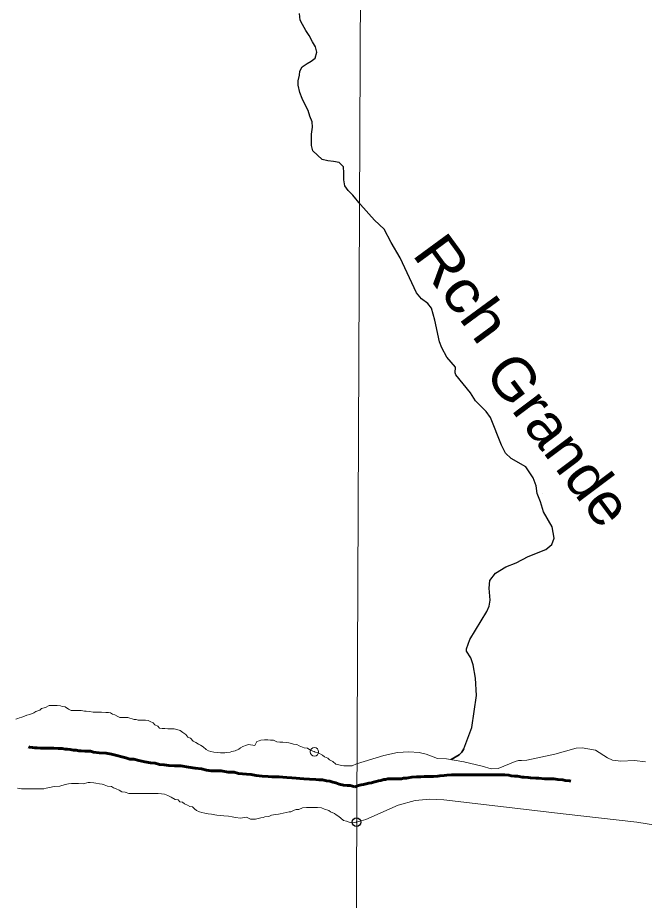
# Model space of a CAD drawing. Extents: x 553962 to 842807, y 8883888 to 9032388.
# Drawn here: x 660513 to 667945, y 8920889 to 8931350 of the extents above; entities that cross this region are included whole.
import ezdxf

# ---------------------------------------------------------------- set-up
doc = ezdxf.new("R2010")
doc.units = 0
doc.header["$LTSCALE"] = 200
doc.header["$PDMODE"] = 32
doc.header["$PDSIZE"] = 100
doc.linetypes.add('LONG_DASH_SHORT_DASH', pattern=[9.9, 6, -1.2, 1.5, -1.2])
for name, color, linetype, lineweight in [('1', 7, 'Continuous', 13), ('24', 7, 'Continuous', 25), ('25', 7, 'Continuous', 13), ('57', 7, 'Continuous', 13), ('7', 7, 'LONG_DASH_SHORT_DASH', 60)]:
    doc.layers.add(name, color=color, linetype=linetype, lineweight=lineweight)
doc.layers.add('49', color=7, linetype='Continuous')

msp = doc.modelspace()

# ---------------------------------------------------------------- linework, layer by layer
at = {"layer": '1'}
msp.add_lwpolyline([(664968.2, 9023436.8), (664657.1, 8949509), (664397.1, 8890880.2)], dxfattribs=at)
at = {"layer": '24'}
msp.add_line((666737.2, 8925710.7), (666737.9, 8925710.1), dxfattribs=at)
for points in [[(663996.4, 8929884.7), (663996.8, 8929971.2), (664009.7, 8930053.7), (664007.4, 8930113.8), (663977.7, 8930184), (663958, 8930249.2), (663913.4, 8930334.5), (663886.1, 8930392.2), (663858.9, 8930462.4), (663839.3, 8930550.1), (663839.5, 8930602.7), (663854.8, 8930667.7), (663860.1, 8930715.2), (663887.8, 8930767.6), (663945.6, 8930807.4), (663995.7, 8930834.6), (664041, 8930869.4), (664061.3, 8930941.9), (664046.6, 8931004.6), (664011.8, 8931064.8), (663969.6, 8931137.6), (663929.9, 8931197.9), (663890.2, 8931270.7), (663862.9, 8931320.8), (663855.7, 8931401)], [(665884.6, 8926902.1), (665710.7, 8927118.6), (665703.5, 8927141.6), (665707.3, 8927207.3), (665604.7, 8927327.2), (665543.5, 8927435.1), (665514.2, 8927508.8), (665462.2, 8927764.8), (665420, 8927905.9), (665377.5, 8927963.9), (665304.4, 8928016.2), (665243.3, 8928087.8), (665050.8, 8928503.2), (664941.5, 8928686.6), (664858.3, 8928844.6), (664746.5, 8928950.8), (664577.8, 8929135.4), (664488.9, 8929245.3), (664434.1, 8929300.7), (664391.8, 8929358.5), (664382.1, 8929428.6), (664380, 8929511.2), (664377.8, 8929583.8), (664325.5, 8929634.1), (664258, 8929647), (664193, 8929654.8), (664125.5, 8929670.2), (664070.7, 8929720.5), (664013.4, 8929773.4), (663996.1, 8929836.1), (663996.4, 8929884.7)], [(665654.1, 8922558.1), (665747.4, 8922613.4), (665782.6, 8922644.9), (665804.2, 8922685), (665898.2, 8922937), (665956.6, 8923316.8), (665944.3, 8923521), (665915.9, 8923680.3), (665887.1, 8923762.6), (665837.8, 8923840.4), (665834.9, 8923868.6), (665876, 8923981.1), (666075.9, 8924311.2), (666104.4, 8924374.8), (666118.2, 8924447.8), (666103.2, 8924589.1), (666111.8, 8924680), (666180.2, 8924767.7), (666303.3, 8924840.7), (666423.2, 8924888.8), (666567, 8924965.4), (666778.1, 8925046.5), (666849.4, 8925104.6), (666875.5, 8925182.5), (666852.3, 8925317.2), (666747.4, 8925494.9), (666714.9, 8925611.2), (666674, 8925709.5), (666660.9, 8925800.8), (666626.8, 8925897.6), (666539.3, 8926027.5), (666367.3, 8926123.4), (666298.2, 8926188.4), (666251.5, 8926283.4), (666120.6, 8926610.3), (666067.4, 8926681.3), (665942.6, 8926807.9), (665884.6, 8926902.1)], [(665804.2, 8922685), (665782.6, 8922644.9), (665747.4, 8922613.4), (665654.1, 8922558.1)]]:
    msp.add_lwpolyline(points, dxfattribs=at)
msp.add_point((664531.1, 8921815.4), dxfattribs=at)
at = {"layer": '25'}
for points in [[(660493.9, 8923037.8), (660516.5, 8923042.7), (660536.6, 8923052.6), (660564.1, 8923059.9), (660596.7, 8923069.7), (660624.3, 8923084.5), (660656.9, 8923089.3), (660704.6, 8923109.1), (660729.7, 8923126.4), (660774.9, 8923143.6), (660797.5, 8923161), (660842.6, 8923175.7), (660885.3, 8923198), (660915.3, 8923197.8), (660940.3, 8923197.6), (660980.4, 8923197.3), (661020.4, 8923194.6), (661042.8, 8923186.9), (661077.8, 8923181.7), (661115.1, 8923156.4), (661147.5, 8923138.7), (661187.5, 8923138.4), (661207.5, 8923138.3), (661245, 8923138), (661265, 8923137.9), (661305, 8923132.6), (661327.5, 8923130), (661365, 8923127.2), (661407.5, 8923119.4), (661447.5, 8923119.2), (661472.5, 8923119), (661507.5, 8923118.8), (661557.5, 8923115.9), (661592.5, 8923113.2), (661615, 8923110.5), (661637.4, 8923095.4), (661667.3, 8923087.7), (661702.2, 8923067.4), (661724.6, 8923057.2), (661754.6, 8923057), (661819.7, 8923056.6), (661897, 8923033.6), (661919.5, 8923030.9), (661942, 8923025.8), (661972, 8923023.1), (662009.5, 8923022.8), (662029.5, 8923022.7), (662062, 8923019.9), (662086.9, 8923009.8), (662121.8, 8922992), (662141.6, 8922969.4), (662176.5, 8922954.1), (662193.8, 8922928.9), (662226.3, 8922923.7), (662258.8, 8922923.5), (662293.8, 8922923.3), (662313.9, 8922923.2), (662333.9, 8922923), (662371.4, 8922922.8), (662401.3, 8922912.6), (662438.7, 8922899.8), (662471.1, 8922879.6), (662508.4, 8922854.3), (662530.7, 8922824.1), (662563.1, 8922808.8), (662592.9, 8922776.1), (662625.2, 8922758.4), (662657.6, 8922738.1), (662680, 8922728), (662712.4, 8922707.7), (662747.2, 8922674.9), (662777.1, 8922659.7), (662804.5, 8922652), (662839.5, 8922644.3), (662884.5, 8922639), (662917, 8922638.8), (662937, 8922638.6), (662969.5, 8922638.4), (662992, 8922640.8), (663032.1, 8922645.5), (663054.6, 8922652.9), (663094.7, 8922662.6), (663134.9, 8922679.9), (663155, 8922697.3), (663182.6, 8922712.1), (663225.3, 8922729.4), (663250.3, 8922734.2), (663325.3, 8922723.7), (663348.2, 8922771.1), (663378.2, 8922778.4)], [(663378.2, 8922778.4), (663398.3, 8922785.8), (663440.8, 8922790.5), (663478.4, 8922790.3), (663513.3, 8922787.5), (663545.9, 8922787.3), (663588.2, 8922767), (663623.2, 8922764.3), (663658.2, 8922764.1), (663698.2, 8922761.3), (663730.7, 8922753.6), (663760.7, 8922748.3), (663785.6, 8922740.7), (663825.6, 8922735.4), (663850.5, 8922720.2), (663890.4, 8922704.9), (663912.8, 8922697.3), (663950.3, 8922692), (663977.7, 8922674.3), (664032.5, 8922648.9), (664084.9, 8922631), (664127.3, 8922608.2), (664152.1, 8922590.5), (664192, 8922572.8), (664211.9, 8922552.6), (664249.2, 8922534.8), (664286.5, 8922504.5), (664309, 8922496.9), (664348.9, 8922486.6), (664381.4, 8922481.4), (664416.4, 8922481.1), (664436.4, 8922481), (664461.5, 8922483.3), (664481.5, 8922483.2), (664531.1, 8922504.7), (664855.7, 8922606.1), (665018.2, 8922640.1), (665151.9, 8922649.8), (665276.6, 8922642.6), (665359.5, 8922619.8)], [(665807.2, 8922530.5), (665805.3, 8922529), (666021.2, 8922480.8), (666128.1, 8922448.4), (666212.6, 8922450.2), (666414.1, 8922533.6), (666451.7, 8922544.9), (666486.4, 8922546.2), (666551.6, 8922551.4), (666883.2, 8922619.3), (667134.9, 8922692.2), (667207.8, 8922696.8), (667366, 8922668.8), (667507, 8922579.6), (667567.9, 8922550.4), (667666.3, 8922536.7), (667827.1, 8922544.8), (667960.2, 8922528.3)], [(665359.5, 8922619.8), (665492.3, 8922568.3), (665600, 8922565.9), (665805.3, 8922529)], [(662255.4, 8922147.4), (662220.4, 8922150.2), (662177.9, 8922153), (662152.9, 8922153.1), (662112.9, 8922153.4), (662087.9, 8922153.6), (662027.9, 8922154), (661975.4, 8922154.3), (661940.3, 8922154.5), (661900.3, 8922154.8), (661872.8, 8922155), (661830.3, 8922155.3), (661790.4, 8922170.6), (661750.4, 8922175.8), (661715.6, 8922196.1), (661683.2, 8922211.3), (661648.2, 8922221.6), (661625.8, 8922236.7), (661578.3, 8922242.1), (661538.5, 8922257.3), (661516, 8922265), (661483.5, 8922270.2), (661441.1, 8922278), (661416.1, 8922283.2), (661373.6, 8922283.5), (661351.1, 8922283.6), (661290.9, 8922269), (661233.5, 8922274.4), (661178.4, 8922274.7), (661150.9, 8922272.4), (661115.8, 8922267.6), (661075.8, 8922260.4), (661015.6, 8922243.3), (660945.6, 8922238.7), (660892.9, 8922224.1), (660852.8, 8922216.8), (660825.3, 8922212), (660772.8, 8922209.8), (660732.7, 8922210.1), (660682.7, 8922210.4), (660637.7, 8922210.7), (660610.2, 8922210.9), (660560.2, 8922211.2), (660510.2, 8922219.1)], [(663096.2, 8921869), (663056.2, 8921876.8), (663013.8, 8921884.6), (662958.8, 8921889.9), (662913.8, 8921895.2), (662873.8, 8921898), (662851.3, 8921903.2), (662811.4, 8921908.4), (662773.9, 8921913.7), (662733.9, 8921921.5), (662696.5, 8921929.2), (662671.5, 8921936.9), (662634.1, 8921952.2), (662611.8, 8921972.3), (662586.9, 8921997.5), (662557, 8922002.8), (662529.6, 8922017.9), (662492.2, 8922033.2), (662469.8, 8922050.9), (662434.8, 8922056.1), (662415, 8922081.3), (662380, 8922084), (662332.7, 8922111.9), (662292.8, 8922132.2), (662255.4, 8922147.4)], [(670613, 8921062.4), (670594.6, 8921075.1), (670505.7, 8921092.1), (670378.9, 8921097.7), (670172.5, 8921136.1), (669790.2, 8921268), (669181.6, 8921455.5), (668940.4, 8921522.2), (668553.3, 8921609.1), (668470.6, 8921646), (668322.8, 8921739.3), (667855.1, 8921816.8), (666980.9, 8921915.9), (665565.9, 8922078.1), (665402.5, 8922087.8), (665227.8, 8922071.5), (665027.5, 8922015.6), (664640.9, 8921845.5), (664531.1, 8921815.4)], [(664531.1, 8921815.4), (664483.8, 8921807.2), (664446.4, 8921815), (664411.5, 8921827.8), (664379, 8921835.5), (664344.2, 8921863.2), (664321.8, 8921880.9), (664292, 8921903.7), (664269.6, 8921918.8), (664224.7, 8921936.6), (664202.3, 8921954.3), (664152.4, 8921969.7), (664117.5, 8921984.9), (664070, 8921987.7), (664027.5, 8921988), (663982.5, 8921988.3), (663937.5, 8921988.6), (663892.4, 8921983.9), (663849.7, 8921964.2), (663814.7, 8921964.4), (663792.2, 8921957), (663754.5, 8921937.2), (663734.5, 8921937.4), (663696.9, 8921930.1), (663661.8, 8921922.8), (663626.8, 8921915.6), (663606.7, 8921910.7), (663571.7, 8921905.9), (663524.1, 8921898.7), (663491.5, 8921883.9), (663446.4, 8921879.2), (663426.3, 8921871.8), (663396.3, 8921867), (663366.2, 8921857.2), (663333.7, 8921852.4), (663311.1, 8921850.1), (663276.1, 8921850.3), (663226.3, 8921875.7), (663156.2, 8921863.6), (663096.2, 8921869)]]:
    msp.add_lwpolyline(points, dxfattribs=at)
msp.add_point((664531.1, 8921815.4), dxfattribs=at)
at = {"layer": '57'}
for points in [[(660493.9, 8923037.8), (660516.5, 8923042.7), (660536.6, 8923052.6), (660564.1, 8923059.9), (660596.7, 8923069.7), (660624.3, 8923084.5), (660656.9, 8923089.3), (660704.6, 8923109.1), (660729.7, 8923126.4), (660774.9, 8923143.6), (660797.5, 8923161), (660842.6, 8923175.7), (660885.3, 8923198), (660915.3, 8923197.8), (660940.3, 8923197.6), (660980.4, 8923197.3), (661020.4, 8923194.6), (661042.8, 8923186.9), (661077.8, 8923181.7), (661115.1, 8923156.4), (661147.5, 8923138.7), (661187.5, 8923138.4), (661207.5, 8923138.3), (661245, 8923138), (661265, 8923137.9), (661305, 8923132.6), (661327.5, 8923130), (661365, 8923127.2), (661407.5, 8923119.4), (661447.5, 8923119.2), (661472.5, 8923119), (661507.5, 8923118.8), (661557.5, 8923115.9), (661592.5, 8923113.2), (661615, 8923110.5), (661637.4, 8923095.4), (661667.3, 8923087.7), (661702.2, 8923067.4), (661724.6, 8923057.2), (661754.6, 8923057), (661819.7, 8923056.6), (661897, 8923033.6), (661919.5, 8923030.9), (661942, 8923025.8), (661972, 8923023.1), (662009.5, 8923022.8), (662029.5, 8923022.7), (662062, 8923019.9), (662086.9, 8923009.8), (662121.8, 8922992), (662141.6, 8922969.4), (662176.5, 8922954.1), (662193.8, 8922928.9), (662226.3, 8922923.7), (662258.8, 8922923.5), (662293.8, 8922923.3), (662313.9, 8922923.2), (662333.9, 8922923), (662371.4, 8922922.8), (662401.3, 8922912.6), (662438.7, 8922899.8), (662471.1, 8922879.6), (662508.4, 8922854.3), (662530.7, 8922824.1), (662563.1, 8922808.8), (662592.9, 8922776.1), (662625.2, 8922758.4), (662657.6, 8922738.1), (662680, 8922728), (662712.4, 8922707.7), (662747.2, 8922674.9), (662777.1, 8922659.7), (662804.5, 8922652), (662839.5, 8922644.3), (662884.5, 8922639), (662917, 8922638.8), (662937, 8922638.6), (662969.5, 8922638.4), (662992, 8922640.8), (663032.1, 8922645.5), (663054.6, 8922652.9), (663094.7, 8922662.6), (663134.9, 8922679.9), (663155, 8922697.3), (663182.6, 8922712.1), (663225.3, 8922729.4), (663250.3, 8922734.2), (663325.3, 8922723.7), (663348.2, 8922771.1), (663378.2, 8922778.4)], [(663378.2, 8922778.4), (663398.3, 8922785.8), (663440.8, 8922790.5), (663478.4, 8922790.3), (663513.3, 8922787.5), (663545.9, 8922787.3), (663588.2, 8922767), (663623.2, 8922764.3), (663658.2, 8922764.1), (663698.2, 8922761.3), (663730.7, 8922753.6), (663760.7, 8922748.3), (663785.6, 8922740.7), (663825.6, 8922735.4), (663850.5, 8922720.2), (663890.4, 8922704.9), (663912.8, 8922697.3), (663950.3, 8922692), (663977.7, 8922674.3), (664032.5, 8922648.9)], [(664032.5, 8922648.9), (664084.9, 8922631), (664127.3, 8922608.2), (664152.1, 8922590.5), (664192, 8922572.8), (664211.9, 8922552.6), (664249.2, 8922534.8), (664286.5, 8922504.5), (664309, 8922496.9), (664348.9, 8922486.6), (664381.4, 8922481.4), (664416.4, 8922481.1), (664436.4, 8922481), (664461.5, 8922483.3), (664481.5, 8922483.2), (664531.1, 8922504.7), (664855.7, 8922606.1), (665018.2, 8922640.1), (665151.9, 8922649.8), (665276.6, 8922642.6), (665359.5, 8922619.8), (665492.3, 8922568.3), (665600, 8922565.9), (665805.3, 8922529), (665807.2, 8922530.5)], [(665807.2, 8922530.5), (665805.3, 8922529), (666021.2, 8922480.8), (666128.1, 8922448.4), (666212.6, 8922450.2), (666414.1, 8922533.6), (666451.7, 8922544.9), (666486.4, 8922546.2), (666551.6, 8922551.4), (666883.2, 8922619.3), (667134.9, 8922692.2), (667207.8, 8922696.8), (667366, 8922668.8), (667507, 8922579.6), (667567.9, 8922550.4), (667666.3, 8922536.7), (667827.1, 8922544.8), (667960.2, 8922528.3)]]:
    msp.add_lwpolyline(points, dxfattribs=at)
msp.add_point((664032.5, 8922648.9), dxfattribs=at)
at = {"layer": '7'}
for points in [[(663706.2, 8922345.6), (663656.3, 8922348.3), (663616.3, 8922351.1), (663591.3, 8922351.2), (663566.3, 8922353.8), (663526.3, 8922354), (663483.8, 8922356.8), (663411.3, 8922362.1), (663341.4, 8922367.5), (663281.5, 8922380.3), (663226.5, 8922383.1), (663181.5, 8922388.4), (663134.1, 8922393.7), (663081.6, 8922406.4), (663011.7, 8922409.3), (662926.8, 8922422.3), (662864.2, 8922422.6), (662806.8, 8922425.4), (662751.8, 8922430.7), (662691.9, 8922448.5), (662617, 8922453.9), (662539.5, 8922466.8), (662447.1, 8922482.4), (662372.1, 8922482.8), (662304.7, 8922488.1), (662249.7, 8922493.4), (662197.2, 8922498.7), (662142.3, 8922514), (662087.4, 8922516.8), (662020, 8922529.7), (661950.1, 8922547.6), (661892.6, 8922560.4), (661845.2, 8922563.1), (661797.8, 8922575.9), (661750.3, 8922591.1), (661690.5, 8922606.5), (661625.6, 8922621.8), (661563.1, 8922634.7), (661478.2, 8922637.6), (661413.2, 8922643), (661378.3, 8922655.7), (661338.3, 8922655.9), (661310.8, 8922656), (661268.3, 8922658.8), (661238.3, 8922661.4), (661205.8, 8922666.6), (661175.9, 8922669.3), (661135.9, 8922677), (661105.9, 8922679.6), (661076, 8922682.3), (661041, 8922687.5), (660993.5, 8922687.7), (660941, 8922690.5), (660893.5, 8922693.3), (660841, 8922693.6), (660786, 8922693.8), (660746, 8922696.6), (660718.5, 8922696.7), (660691.1, 8922701.8), (660648.6, 8922704.6), (660641.7, 8922706.3)], [(664555.3, 8922251.1), (664510.5, 8922233.7), (664455.6, 8922249), (664420.6, 8922251.7), (664375.7, 8922254.4), (664325.7, 8922267.2), (664288.3, 8922282.4), (664250.9, 8922287.6), (664213.5, 8922300.3), (664176, 8922305.6), (664128.6, 8922318.3), (664086.1, 8922318.5), (664048.6, 8922321.2), (663973.6, 8922324.1), (663908.6, 8922327), (663861.2, 8922332.2), (663816.2, 8922335), (663763.7, 8922340.3), (663706.2, 8922345.6)], [(666977.6, 8922317.6), (666919.1, 8922320.2), (666870.8, 8922327.8), (666842.8, 8922327.8), (666799.5, 8922330.4), (666761.3, 8922330.4), (666692.6, 8922335.5), (666657, 8922338), (666595.9, 8922340.6), (666565.4, 8922345.7), (666519.6, 8922348.3), (666496.7, 8922348.3), (666461.1, 8922355.9), (666440.7, 8922358.5), (666405.1, 8922361), (666366.9, 8922366.2), (666338.9, 8922371.3), (666290.6, 8922376.4), (666227, 8922376.4), (666168.5, 8922376.4), (666140.5, 8922376.4), (666092.1, 8922376.4), (666061.6, 8922376.4), (665980.2, 8922376.4), (665944.5, 8922376.4), (665886, 8922376.4), (665855.5, 8922376.4), (665799.5, 8922376.4), (665769, 8922376.4), (665697.7, 8922376.4), (665659.6, 8922376.4), (665601, 8922371.2), (665570.5, 8922368.7), (665519.6, 8922366.1), (665494.2, 8922361), (665443.3, 8922355.9), (665400, 8922355.9), (665377.1, 8922355.9), (665333.9, 8922355.9), (665293.2, 8922350.8), (665244.8, 8922350.8), (665188.8, 8922348.2), (665145.6, 8922340.6), (665122.7, 8922338), (665087.1, 8922335.5), (665066.7, 8922330.3), (665018.4, 8922327.8), (664987.8, 8922327.8), (664962.4, 8922327.8), (664934.4, 8922327.8), (664903.9, 8922327.8), (664875.9, 8922320.1), (664855.5, 8922320.1), (664819.9, 8922309.9), (664791.9, 8922304.8), (664763.9, 8922297.1), (664733.4, 8922289.4), (664708, 8922281.8), (664677.4, 8922276.7), (664646.9, 8922269), (664616.4, 8922261.3), (664585.8, 8922256.2), (664555.3, 8922251.1), (664555.3, 8922251.1), (664555.3, 8922251.1)], [(667073.5, 8922301.6), (667059.1, 8922304.8), (667005.6, 8922309.9), (666977.6, 8922317.6)]]:
    msp.add_lwpolyline(points, dxfattribs=at)

# ---------------------------------------------------------------- texts
at = {"layer": '49'}
for s, rotation, width, p in [('Rch', 306.272, 1.15, (665180.9, 8928547.7)), ('Grande', 306.886, 1.05, (666032.2, 8927138.1))]:
    msp.add_text(s, height=500, rotation=rotation, dxfattribs=dict(at, width=width)).set_placement(p)

doc.saveas('drawing.dxf')
